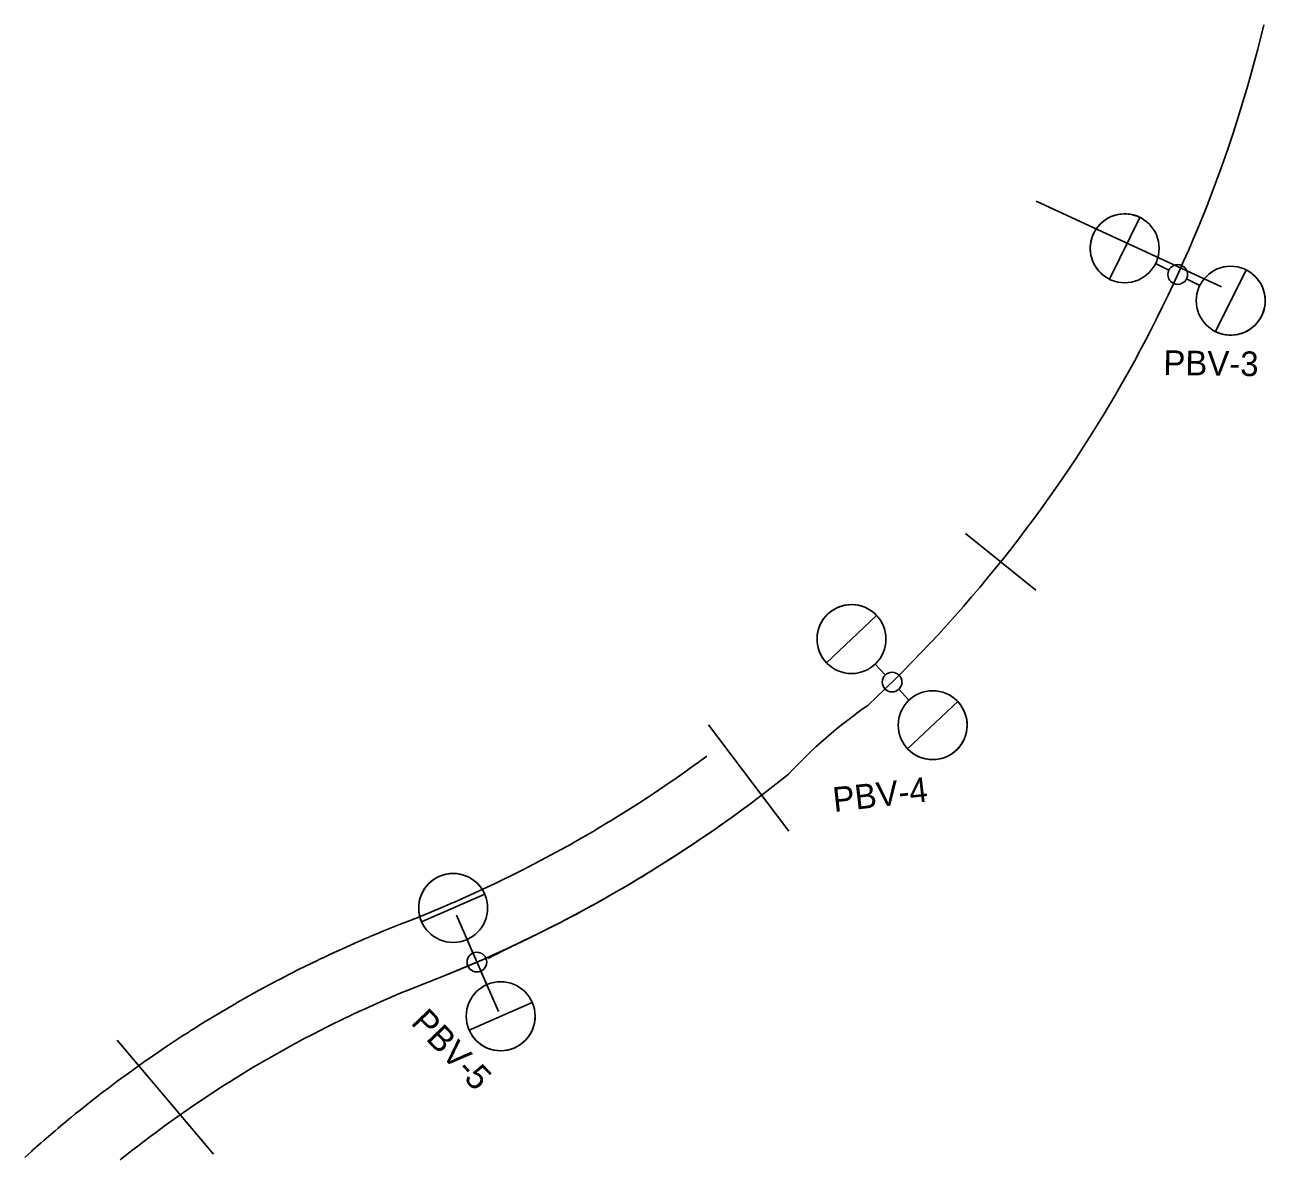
# Model space of a CAD drawing. Extents: x 0 to 511877, y 0 to 6211921.
# Drawn here: x 511575.1 to 511638, y 6211675.4 to 6211732.8 of the extents above; entities that cross this region are included whole.
import ezdxf

# ---------------------------------------------------------------- set-up
doc = ezdxf.new("R2010")
doc.units = 0
for name, color, linetype in [('Help', 7, 'Continuous'), ('TV_U_LYS_Ledn-', 7, 'Continuous'), ('TV_U_LYS_Mastenummer', 7, 'Continuous'), ('TV_U_LYS_Nyx330-Boligvej', 7, 'Continuous')]:
    doc.layers.add(name, color=color, linetype=linetype)

msp = doc.modelspace()

# ---------------------------------------------------------------- linework, layer by layer
at = {"layer": 'Help'}
for p, q in [((511626.416, 6211723.882), (511635.832, 6211719.517)), ((511622.821, 6211706.997), (511626.395, 6211704.117)), ((511609.773, 6211697.277), (511613.856, 6211691.886)), ((511596.974, 6211687.613), (511599.111, 6211682.729)), ((511579.743, 6211681.271), (511584.634, 6211675.482))]:
    msp.add_line(p, q, dxfattribs=at)
for points in [[(511609.697, 6211695.695), (511609.202, 6211695.333), (511608.799, 6211695.044), (511608.565, 6211694.878), (511608.467, 6211694.809), (511608.348, 6211694.726), (511607.906, 6211694.418), (511607.732, 6211694.3), (511606.962, 6211693.781), (511606.907, 6211693.745), (511606.713, 6211693.617), (511606.532, 6211693.498), (511606.213, 6211693.292), (511606.082, 6211693.207), (511605.45, 6211692.808), (511604.959, 6211692.504), (511604.817, 6211692.417), (511604.683, 6211692.336), (511604.213, 6211692.054), (511604.203, 6211692.048), (511603.913, 6211691.876), (511603.111, 6211691.413), (511602.981, 6211691.339), (511602.882, 6211691.283), (511602.792, 6211691.232), (511602.326, 6211690.973), (511602.298, 6211690.957), (511601.535, 6211690.544), (511600.952, 6211690.236), (511600.909, 6211690.214), (511600.862, 6211690.19), (511600.741, 6211690.127), (511600.339, 6211689.921), (511599.936, 6211689.718), (511599.108, 6211689.312), (511598.907, 6211689.215), (511598.35, 6211688.952), (511598.313, 6211688.935), (511597.471, 6211688.55), (511597.094, 6211688.382), (511596.875, 6211688.286), (511596.865, 6211688.282), (511596.849, 6211688.274), (511596.837, 6211688.269), (511596.727, 6211688.222), (511596.654, 6211688.19), (511596.349, 6211688.059), (511595.818, 6211687.835), (511595.272, 6211687.61), (511595.166, 6211687.567), (511594.98, 6211687.492), (511594.838, 6211687.435), (511594.813, 6211687.425), (511594.78, 6211687.412), (511594.756, 6211687.403), (511594.536, 6211687.316), (511594.298, 6211687.223), (511594.085, 6211687.14), (511593.155, 6211686.766), (511593.045, 6211686.721), (511592.585, 6211686.529), (511592.568, 6211686.521), (511592.506, 6211686.495), (511592.491, 6211686.489), (511592.311, 6211686.412), (511592.102, 6211686.322), (511591.998, 6211686.276), (511590.996, 6211685.83), (511590.652, 6211685.671), (511590.308, 6211685.511), (511590.238, 6211685.478), (511590.234, 6211685.476), (511590.167, 6211685.444), (511590.105, 6211685.414), (511589.965, 6211685.348), (511589.915, 6211685.324), (511588.955, 6211684.853), (511588.205, 6211684.47), (511588.058, 6211684.394), (511587.993, 6211684.36), (511587.949, 6211684.337), (511587.935, 6211684.329), (511587.927, 6211684.325), (511587.868, 6211684.295), (511587.789, 6211684.253), (511586.952, 6211683.803), (511585.986, 6211683.262), (511585.845, 6211683.181), (511585.784, 6211683.146), (511585.781, 6211683.145), (511585.772, 6211683.139), (511585.716, 6211683.107), (511585.667, 6211683.078), (511585.596, 6211683.037), (511584.992, 6211682.682), (511584.083, 6211682.129), (511584.029, 6211682.096), (511583.682, 6211681.879), (511583.672, 6211681.872), (511583.667, 6211681.869), (511583.61, 6211681.833), (511583.442, 6211681.726), (511583.397, 6211681.698), (511583.377, 6211681.685), (511583.071, 6211681.489), (511582.149, 6211680.881), (511581.691, 6211680.569), (511581.603, 6211680.509), (511581.536, 6211680.463), (511581.481, 6211680.425), (511581.261, 6211680.272), (511581.212, 6211680.238), (511581.203, 6211680.232), (511581.058, 6211680.13), (511580.297, 6211679.586), (511579.751, 6211679.185), (511579.581, 6211679.057), (511579.453, 6211678.962), (511579.405, 6211678.926), (511579.384, 6211678.909), (511579.131, 6211678.717), (511579.075, 6211678.675), (511578.8, 6211678.463), (511578.489, 6211678.221), (511577.866, 6211677.726), (511577.618, 6211677.525), (511577.604, 6211677.514), (511577.424, 6211677.367), (511577.374, 6211677.326), (511577.058, 6211677.065), (511577.007, 6211677.021), (511576.747, 6211676.804), (511576.589, 6211676.669), (511576.039, 6211676.197), (511575.89, 6211676.066), (511575.689, 6211675.89), (511575.453, 6211675.68), (511575.406, 6211675.638), (511575.056, 6211675.322)], [(511611.615, 6211693.072), (511611.109, 6211692.701), (511610.687, 6211692.399), (511610.441, 6211692.224), (511610.337, 6211692.151), (511610.208, 6211692.06), (511609.751, 6211691.743), (511609.559, 6211691.611), (511608.767, 6211691.078), (511608.699, 6211691.033), (511608.497, 6211690.9), (511608.305, 6211690.775), (511607.975, 6211690.56), (511607.828, 6211690.466), (511607.173, 6211690.052), (511606.661, 6211689.735), (511606.508, 6211689.642), (511606.365, 6211689.555), (511606.363, 6211689.553), (511605.88, 6211689.264), (511605.86, 6211689.252), (511605.553, 6211689.07), (511604.727, 6211688.593), (511604.583, 6211688.511), (511604.478, 6211688.452), (511604.379, 6211688.396), (511603.9, 6211688.13), (511603.856, 6211688.105), (511603.067, 6211687.678), (511602.46, 6211687.358), (511602.409, 6211687.331), (511602.358, 6211687.304), (511602.229, 6211687.237), (511601.81, 6211687.023), (511601.383, 6211686.808), (511600.527, 6211686.388), (511600.304, 6211686.281), (511599.73, 6211686.01), (511599.675, 6211685.984), (511598.808, 6211685.588), (511598.408, 6211685.41), (511598.18, 6211685.309), (511598.167, 6211685.304), (511598.149, 6211685.296), (511598.136, 6211685.29), (511598.023, 6211685.241), (511597.942, 6211685.206), (511597.623, 6211685.069), (511597.068, 6211684.835), (511596.501, 6211684.601), (511596.383, 6211684.554), (511596.189, 6211684.475), (511596.041, 6211684.416), (511596.014, 6211684.405), (511595.979, 6211684.392), (511595.951, 6211684.381), (511595.724, 6211684.291), (511595.48, 6211684.196), (511595.281, 6211684.118), (511594.381, 6211683.756), (511594.292, 6211683.72), (511593.846, 6211683.533), (511593.835, 6211683.529), (511593.776, 6211683.503), (511593.765, 6211683.499), (511593.592, 6211683.425), (511593.392, 6211683.339), (511593.306, 6211683.302), (511592.337, 6211682.87), (511592.02, 6211682.723), (511591.69, 6211682.569), (511591.626, 6211682.539), (511591.624, 6211682.538), (511591.56, 6211682.508), (511591.502, 6211682.48), (511591.368, 6211682.416), (511591.333, 6211682.399), (511590.409, 6211681.946), (511589.693, 6211681.581), (511589.561, 6211681.512), (511589.5, 6211681.48), (511589.458, 6211681.458), (511589.445, 6211681.451), (511589.438, 6211681.448), (511589.382, 6211681.419), (511589.316, 6211681.384), (511588.515, 6211680.953), (511587.587, 6211680.434), (511587.463, 6211680.363), (511587.406, 6211680.33), (511587.404, 6211680.329), (511587.396, 6211680.324), (511587.343, 6211680.293), (511587.296, 6211680.266), (511587.235, 6211680.231), (511586.66, 6211679.893), (511585.784, 6211679.36), (511585.748, 6211679.337), (511585.411, 6211679.126), (511585.405, 6211679.123), (511585.402, 6211679.121), (511585.348, 6211679.087), (511585.186, 6211678.984), (511585.144, 6211678.957), (511585.13, 6211678.948), (511584.844, 6211678.765), (511583.957, 6211678.18), (511583.523, 6211677.885), (511583.445, 6211677.832), (511583.381, 6211677.788), (511583.332, 6211677.754), (511583.118, 6211677.605), (511583.074, 6211677.574), (511583.067, 6211677.57), (511582.937, 6211677.478), (511582.205, 6211676.955), (511581.685, 6211676.573), (511581.528, 6211676.456), (511581.407, 6211676.364), (511581.362, 6211676.331), (511581.345, 6211676.318), (511581.1, 6211676.132), (511581.052, 6211676.096), (511580.789, 6211675.893), (511580.498, 6211675.666), (511579.899, 6211675.191)]]:
    msp.add_lwpolyline(points, dxfattribs=at)
at = {"layer": 'TV_U_LYS_Ledn-'}
msp.add_line((511596.442, 6211684.577), (511598.014, 6211685.237), dxfattribs=at)
msp.add_lwpolyline([(511596.442, 6211684.577), (511596.383, 6211684.554), (511596.189, 6211684.475), (511596.041, 6211684.416), (511596.014, 6211684.405), (511595.979, 6211684.392), (511595.951, 6211684.381), (511595.724, 6211684.291), (511595.48, 6211684.196), (511595.281, 6211684.118), (511594.381, 6211683.756), (511594.292, 6211683.72), (511593.846, 6211683.533), (511593.835, 6211683.529), (511593.776, 6211683.503), (511593.765, 6211683.499), (511593.592, 6211683.425), (511593.392, 6211683.339), (511593.306, 6211683.302), (511592.337, 6211682.87), (511592.02, 6211682.723), (511591.69, 6211682.569), (511591.626, 6211682.539), (511591.624, 6211682.538), (511591.56, 6211682.508), (511591.502, 6211682.48), (511591.368, 6211682.416), (511591.333, 6211682.399), (511590.409, 6211681.946), (511589.693, 6211681.581), (511589.561, 6211681.512), (511589.5, 6211681.48), (511589.458, 6211681.458), (511589.445, 6211681.451), (511589.438, 6211681.448), (511589.382, 6211681.419), (511589.316, 6211681.384), (511588.515, 6211680.953), (511587.587, 6211680.434), (511587.463, 6211680.363), (511587.406, 6211680.33), (511587.404, 6211680.329), (511587.396, 6211680.324), (511587.343, 6211680.293), (511587.296, 6211680.266), (511587.235, 6211680.231), (511586.66, 6211679.893), (511585.784, 6211679.36), (511585.748, 6211679.337), (511585.411, 6211679.126), (511585.405, 6211679.123), (511585.402, 6211679.121), (511585.348, 6211679.087), (511585.186, 6211678.984), (511585.144, 6211678.957), (511585.13, 6211678.948), (511584.844, 6211678.765), (511583.957, 6211678.18), (511583.523, 6211677.885), (511583.445, 6211677.832), (511583.381, 6211677.788), (511583.332, 6211677.754), (511583.118, 6211677.605), (511583.074, 6211677.574), (511583.067, 6211677.57), (511582.937, 6211677.478), (511582.205, 6211676.955), (511581.685, 6211676.573), (511581.528, 6211676.456), (511581.407, 6211676.364), (511581.362, 6211676.331), (511581.345, 6211676.318), (511581.1, 6211676.132), (511581.052, 6211676.096), (511580.789, 6211675.893), (511580.498, 6211675.666), (511579.899, 6211675.191)], dxfattribs=at)
for centre, radius, start, end in [((511570.292, 6211749.089), 69.61, 313.10313, 346.49238), ((511631.638, 6211678.293), 24.265, 124.60554, 137.21361), ((511570.292, 6211749.089), 69.61, 295.53938, 308.71602), ((511629.943, 6211624.248), 68.75, 115.53938, 117.1432)]:
    msp.add_arc(centre, radius, start, end, dxfattribs=at)
at = {"layer": 'TV_U_LYS_Nyx330-Boligvej'}
for p, q in [((511630.132, 6211719.913), (511631.686, 6211723.052)), ((511633.152, 6211720.372), (511632.48, 6211720.706)), ((511637.071, 6211720.389), (511635.518, 6211717.25)), ((511637.071, 6211720.389), (511637.071, 6211720.389)), ((511630.132, 6211719.913), (511630.132, 6211719.913)), ((511634.051, 6211719.93), (511634.724, 6211719.595)), ((511615.761, 6211700.438), (511618.311, 6211702.841)), ((511615.761, 6211700.438), (511615.761, 6211700.438)), ((511618.753, 6211699.818), (511618.238, 6211700.365)), ((511619.441, 6211699.09), (511619.955, 6211698.542)), ((511622.432, 6211698.469), (511619.883, 6211696.067)), ((511622.432, 6211698.469), (511622.432, 6211698.469)), ((511595.202, 6211687.284), (511598.41, 6211688.691)), ((511595.202, 6211687.284), (511595.202, 6211687.284)), ((511597.812, 6211685.695), (511597.511, 6211686.384)), ((511598.216, 6211684.779), (511598.516, 6211684.09)), ((511600.825, 6211683.19), (511597.617, 6211681.783)), ((511600.825, 6211683.19), (511600.825, 6211683.19))]:
    msp.add_line(p, q, dxfattribs=at)
for centre, radius in [((511630.91, 6211721.482), 1.75), ((511633.602, 6211720.151), 0.5), ((511633.602, 6211720.151), 0.5), ((511636.294, 6211718.82), 1.75), ((511617.037, 6211701.639), 1.75), ((511619.097, 6211699.454), 0.5), ((511619.097, 6211699.454), 0.5), ((511621.157, 6211697.269), 1.75), ((511596.807, 6211687.987), 1.75), ((511598.014, 6211685.237), 0.5), ((511598.014, 6211685.237), 0.5), ((511599.221, 6211682.487), 1.75)]:
    msp.add_circle(centre, radius, dxfattribs=at)
for centre, start, end in [((511630.91, 6211721.482), 63.70624, 243.63627), ((511636.294, 6211718.82), 243.70624, 63.63627), ((511617.037, 6211701.639), 43.33131, 223.26134), ((511621.157, 6211697.269), 223.33131, 43.26134), ((511596.807, 6211687.987), 23.71349, 203.64352), ((511599.221, 6211682.487), 203.71349, 23.64352)]:
    msp.add_arc(centre, 1.75, start, end, dxfattribs=at)

# ---------------------------------------------------------------- texts
at = {"layer": 'TV_U_LYS_Mastenummer'}
for s, rotation, p in [('PBV-3', 359.19064, (511632.867, 6211715.056)), ('PBV-4', 6.39476, (511616.156, 6211692.857)), ('PBV-5', 313.72936, (511594.613, 6211682.122))]:
    msp.add_text(s, height=1.25, rotation=rotation, dxfattribs=at).set_placement(p)

doc.saveas('drawing.dxf')
